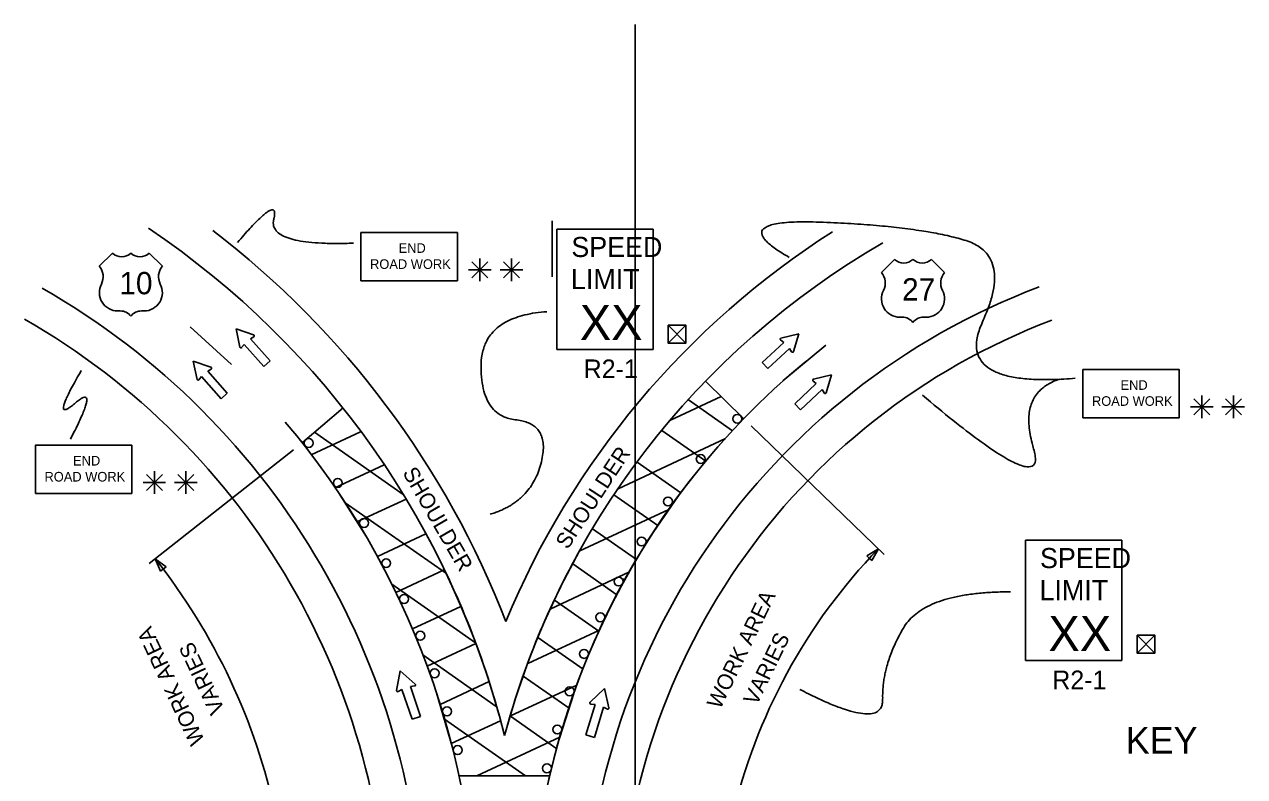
# Model space of a CAD drawing. Extents: x 16731 to 18475, y 7005 to 8303.
# Drawn here: x 16750 to 17297, y 7966 to 8303 of the extents above; entities that cross this region are included whole.
import ezdxf

# ---------------------------------------------------------------- set-up
doc = ezdxf.new("R2010")
doc.units = 0
for name, color, linetype in [('ALI_LEGAL_EX', 7, 'Continuous'), ('MT_SCRATCH_LEVEL_A', 7, 'Continuous'), ('MT_SCRATCH_LEVEL_E', 7, 'Continuous'), ('PAVT_EDGE_EX', 7, 'Continuous'), ('TRAFFIC_SIGNS_PR', 7, 'Continuous'), ('TYPICAL_EX', 7, 'Continuous'), ('TYPICAL_TEXT_DIMEN_EX', 7, 'Continuous'), ('TYPICAL_TEXT_DIMEN_PR', 7, 'Continuous')]:
    doc.layers.add(name, color=color, linetype=linetype)

msp = doc.modelspace()

# ---------------------------------------------------------------- linework, layer by layer
at = {"layer": 'ALI_LEGAL_EX'}
msp.add_line((17024.17, 8303.41), (17024.17, 7485.27), dxfattribs=at)
for points in [[(17024.17, 8278.41), (17024.17, 8303.41)], [(16987.01, 8190.21), (16987.01, 8215.21)], [(16843.15, 8150.81), (16824.71, 8167.69)], [(17090.38, 8143.53), (17109.68, 8159.42)], [(16904.53, 8072.26), (16891.17, 8093.39)], [(17029.34, 8071.03), (17043.42, 8091.69)], [(16942.06, 7979.47), (16935.11, 8003.48)], [(16989.13, 7979.42), (16996.62, 8003.27)]]:
    msp.add_lwpolyline(points, dxfattribs=at)
for centre, radius, start, end in [((17317.23, 7890.11), 340, 129.5666, 180), ((16589.23, 7890.11), 364, 0, 40.1909), ((17317.23, 7890.11), 340, 137.516, 180)]:
    msp.add_arc(centre, radius, start, end, dxfattribs=at)
at = {"layer": 'MT_SCRATCH_LEVEL_A'}
for p, q in [((17072.9, 8126.5), (17055.74, 8143.28)), ((17040, 8125.88), (17062.7, 8136.47)), ((16893.27, 8131.34), (16874.98, 8115.8)), ((17067.86, 8121.02), (17048.06, 8134.89)), ((16878.93, 8110.36), (16901.08, 8120.68)), ((16920.23, 8092.55), (16880.42, 8120.42)), ((17055.85, 8107.46), (17036.22, 8121.2)), ((17016.58, 8095.1), (17064.76, 8117.57)), ((16889.58, 8095.46), (16911.61, 8105.73)), ((17044.7, 8093.29), (17025.06, 8107.04)), ((17034.42, 8078.51), (17014.64, 8092.36)), ((16939.21, 8057.28), (16894.22, 8088.78)), ((16899.45, 8080.2), (16921.43, 8090.45)), ((16999.37, 8067.21), (17039.23, 8085.8)), ((17024.79, 8063.28), (17005.08, 8077.08)), ((16908.64, 8064.63), (16930.39, 8074.77)), ((17015.92, 8047.52), (16996.21, 8061.32)), ((16916.84, 8048.59), (16938.51, 8058.7)), ((16986.3, 8041.26), (17021.63, 8057.73)), ((17019.35, 8054.02), (17018.71, 8054.66)), ((16952.58, 8025.95), (16915.01, 8052.26)), ((17007.93, 8031.14), (16988.04, 8045.07)), ((16924.27, 8032.2), (16945.95, 8042.31)), ((16976.1, 8016.64), (17008.15, 8031.59)), ((17000.82, 8014.15), (16980.57, 8028.32)), ((16930.9, 8015.43), (16952.71, 8025.59)), ((16961.91, 7997.44), (16928.96, 8020.51)), ((16994.52, 7996.58), (16973.94, 8010.99)), ((16936.72, 7998.28), (16958.68, 8008.52)), ((16968.25, 7993.12), (16998.01, 8007)), ((16975.07, 7966.26), (16938.68, 7991.74)), ((16941.61, 7980.7), (16963.73, 7991.01)), ((16989.08, 7978.41), (16968.22, 7993.02)), ((16953.23, 7966.26), (16990.46, 7983.62)), ((16945.18, 7966.26), (16985.87, 7966.26)), ((16945.18, 7966.26), (16985.87, 7966.26)), ((16985.87, 7966.26), (16945.18, 7966.26)), ((16950.52, 7966.26), (16950.55, 7966.21)), ((16957.41, 7966.26), (16957.44, 7966.21)), ((16964.3, 7966.26), (16964.33, 7966.21)), ((16971.18, 7966.26), (16971.21, 7966.21)), ((16978.07, 7966.26), (16978.1, 7966.21)), ((16984.96, 7966.26), (16984.99, 7966.21))]:
    msp.add_line(p, q, dxfattribs=at)
for centre, radius, start, end in [((16589.23, 7890.11), 388, 14.0483, 28.2673), ((16589.23, 7890.11), 388, 14.0483, 28.2673), ((17317.23, 7890.11), 364, 151.1372, 165.0045), ((17317.23, 7890.11), 364, 151.1372, 165.0044)]:
    msp.add_arc(centre, radius, start, end, dxfattribs=at)
at = {"layer": 'MT_SCRATCH_LEVEL_E'}
for p, q in [((16845.2, 8166.75), (16846.93, 8158.61)), ((16853.1, 8164.09), (16845.2, 8166.75)), ((16845.2, 8166.75), (16846.93, 8158.61)), ((16853.1, 8164.09), (16845.2, 8166.75)), ((17097.64, 8164.6), (17089.54, 8162.65)), ((17097.64, 8164.6), (17089.54, 8162.65)), ((17095.19, 8156.63), (17097.64, 8164.6)), ((17095.19, 8156.63), (17097.64, 8164.6)), ((16847.74, 8158.42), (16848.86, 8159.83)), ((16847.74, 8158.42), (16848.86, 8159.83)), ((16848.86, 8159.83), (16857.66, 8149.91)), ((16848.86, 8159.83), (16857.66, 8149.91)), ((16851.66, 8162.31), (16853.2, 8163.26)), ((16851.66, 8162.31), (16853.2, 8163.26)), ((16860.46, 8152.39), (16851.66, 8162.31)), ((16860.46, 8152.39), (16851.66, 8162.31)), ((17090.82, 8160.75), (17081.15, 8151.68)), ((17090.82, 8160.75), (17081.15, 8151.68)), ((17083.71, 8148.95), (17093.38, 8158.02)), ((17083.71, 8148.95), (17093.38, 8158.02)), ((17089.37, 8161.83), (17090.82, 8160.75)), ((17089.37, 8161.83), (17090.82, 8160.75)), ((17093.38, 8158.02), (17094.36, 8156.51)), ((17093.38, 8158.02), (17094.36, 8156.51)), ((16826.05, 8152.29), (16827.77, 8144.14)), ((16833.95, 8149.62), (16826.05, 8152.29)), ((16826.05, 8152.29), (16827.77, 8144.14)), ((16833.95, 8149.62), (16826.05, 8152.29)), ((16832.51, 8147.85), (16834.05, 8148.79)), ((16832.51, 8147.85), (16834.05, 8148.79)), ((16841.3, 8137.93), (16832.51, 8147.85)), ((16841.3, 8137.93), (16832.51, 8147.85)), ((16857.66, 8149.91), (16860.46, 8152.39)), ((16857.66, 8149.91), (16860.46, 8152.39)), ((17081.15, 8151.68), (17083.71, 8148.95)), ((17081.15, 8151.68), (17083.71, 8148.95)), ((16828.59, 8143.95), (16829.71, 8145.37)), ((16828.59, 8143.95), (16829.71, 8145.37)), ((16829.71, 8145.37), (16838.5, 8135.45)), ((16829.71, 8145.37), (16838.5, 8135.45)), ((17105.41, 8142.28), (17095.74, 8133.21)), ((17105.41, 8142.28), (17095.74, 8133.21)), ((17103.97, 8143.36), (17105.41, 8142.28)), ((17103.97, 8143.36), (17105.41, 8142.28)), ((17112.23, 8146.13), (17104.14, 8144.18)), ((17112.23, 8146.13), (17104.14, 8144.18)), ((17109.78, 8138.15), (17112.23, 8146.13)), ((17109.78, 8138.15), (17112.23, 8146.13)), ((16838.5, 8135.45), (16841.3, 8137.93)), ((16838.5, 8135.45), (16841.3, 8137.93)), ((17098.3, 8130.48), (17107.97, 8139.55)), ((17098.3, 8130.48), (17107.97, 8139.55)), ((17107.97, 8139.55), (17108.96, 8138.04)), ((17107.97, 8139.55), (17108.96, 8138.04)), ((17095.74, 8133.21), (17098.3, 8130.48)), ((17095.74, 8133.21), (17098.3, 8130.48))]:
    msp.add_line(p, q, dxfattribs=at)
for centre, start, end in [((16852.95, 8163.65), 301.5941, 71.331), ((16852.95, 8163.65), 301.5941, 71.331), ((16847.38, 8158.71), 191.9827, 321.5217), ((16847.38, 8158.71), 191.9827, 321.5217), ((17089.66, 8162.2), 103.5817, 233.1207), ((17089.66, 8162.2), 103.5817, 233.1207), ((17094.75, 8156.77), 213.193, 342.93), ((17094.75, 8156.77), 213.193, 342.93), ((16833.8, 8149.18), 301.5941, 71.331), ((16833.8, 8149.18), 301.5941, 71.331), ((16828.23, 8144.25), 191.9827, 321.5217), ((16828.23, 8144.25), 191.9827, 321.5217), ((17104.25, 8143.73), 103.5817, 233.1207), ((17104.25, 8143.73), 103.5817, 233.1207), ((17109.34, 8138.3), 213.193, 342.93), ((17109.34, 8138.3), 213.193, 342.93)]:
    msp.add_arc(centre, 0.463, start, end, dxfattribs=at)
at = {"layer": 'PAVT_EDGE_EX'}
for centre, radius, start, end in [((16589.23, 7890.11), 388, 14.0482, 56.0497), ((16589.23, 7890.11), 404, 21.0961, 52.5595), ((17317.23, 7890.11), 380, 122.5612, 157.5011), ((17317.23, 7890.11), 364, 119.9839, 165.0045), ((17317.23, 7890.11), 316, 110.7433, 180), ((16589.23, 7890.11), 340, 0, 60.187), ((16589.23, 7890.11), 324, 0, 60.187), ((17317.23, 7890.11), 300, 110.7433, 180)]:
    msp.add_arc(centre, radius, start, end, dxfattribs=at)
at = {"layer": 'TRAFFIC_SIGNS_PR'}
for p, q in [((16989.09, 8211.57), (17032.29, 8211.57)), ((16989.09, 8157.57), (16989.09, 8211.57)), ((17032.29, 8157.57), (17032.29, 8211.57)), ((16989.09, 8157.57), (17032.29, 8157.57)), ((17199.23, 8072), (17242.43, 8072)), ((17199.23, 8018), (17199.23, 8072)), ((17242.43, 8018), (17242.43, 8072)), ((17199.23, 8018), (17242.43, 8018)), ((17010.42, 8005.42), (17004, 7999.28)), ((17012.44, 7996.75), (17010.42, 8005.42)), ((17006.2, 7998.21), (17002.13, 7984.67)), ((17004.28, 7998.44), (17006.2, 7998.21)), ((17005.96, 7983.52), (17010.02, 7997.07)), ((17010.02, 7997.07), (17011.74, 7996.2)), ((17002.13, 7984.67), (17005.96, 7983.52))]:
    msp.add_line(p, q, dxfattribs=at)
for points in [[(16901.25, 8188.38), (16944.45, 8188.38), (16944.45, 8209.98), (16901.25, 8209.98)], [(17224.95, 8126.93), (17268.15, 8126.93), (17268.15, 8148.53), (17224.95, 8148.53)], [(16755.27, 8092.97), (16798.47, 8092.97), (16798.47, 8114.57), (16755.27, 8114.57)]]:
    msp.add_lwpolyline(points, close=True, dxfattribs=at)
for centre in [(17069.98, 8126.45), (16877.77, 8115.58), (17053.61, 8108.4), (16890.85, 8097.69), (17038.9, 8089.35), (16902.58, 8079.73), (17027.06, 8071.39), (16912.53, 8061.68), (17016.76, 8053.45), (16920.57, 8045.58), (17008.58, 8037.42), (16927.82, 8029.11), (17001.26, 8020.98), (16934.24, 8012.29), (16994.81, 8004.17), (16939.83, 7995.18), (16989.26, 7987.05), (16944.57, 7977.82), (16984.61, 7969.66)]:
    msp.add_circle(centre, 2, dxfattribs=at)
for centre, start, end in [((17004.35, 7998.93), 133.7284, 263.2673), ((17011.95, 7996.65), 243.3397, 13.0766)]:
    msp.add_arc(centre, 0.494, start, end, dxfattribs=at)
at = {"layer": 'TYPICAL_EX'}
for p, q in [((16783.9, 8194.89), (16789.79, 8200.79)), ((16812.2, 8194.89), (16806.3, 8200.79)), ((17134.61, 8192.09), (17140.51, 8197.99)), ((17162.91, 8192.09), (17157.02, 8197.99)), ((16792.14, 8174.83), (16793.32, 8174.83)), ((16803.95, 8174.83), (16802.77, 8174.83)), ((17142.86, 8172.03), (17144.04, 8172.03)), ((17154.67, 8172.03), (17153.49, 8172.03))]:
    msp.add_line(p, q, dxfattribs=at)
for centre, radius, start, end in [((16793.92, 8205.08), 5.96, 226.1404, 313.8596), ((16802.17, 8205.08), 5.96, 226.1404, 313.8596), ((17144.64, 8202.28), 5.96, 226.1404, 313.8596), ((17152.89, 8202.28), 5.96, 226.1404, 313.8596), ((16778.31, 8190.17), 7.31, 333.0977, 40.1936), ((16817.78, 8190.17), 7.31, 139.8064, 206.9023), ((17129.03, 8187.37), 7.31, 333.0977, 40.1936), ((17168.5, 8187.37), 7.31, 139.8064, 206.9023), ((16792.16, 8183.08), 8.24, 152.6698, 269.9013), ((16803.94, 8183.08), 8.24, 270.0987, 27.3302), ((17142.87, 8180.27), 8.24, 152.6698, 269.9013), ((17154.65, 8180.27), 8.24, 270.0987, 27.3302), ((16793.34, 8168.93), 5.91, 37.1038, 90.1385), ((16802.76, 8168.93), 5.91, 89.8615, 142.8962), ((17144.05, 8166.12), 5.91, 37.1038, 90.1385), ((17153.47, 8166.12), 5.91, 89.8615, 142.8962)]:
    msp.add_arc(centre, radius, start, end, dxfattribs=at)
at = {"layer": 'TYPICAL_TEXT_DIMEN_PR'}
for p, q in [((16951.01, 8196.88), (16958.18, 8189.71)), ((16958.18, 8196.88), (16951.01, 8189.71)), ((16954.6, 8193.3), (16954.6, 8198.31)), ((16965.14, 8196.88), (16972.31, 8189.71)), ((16972.31, 8196.88), (16965.14, 8189.71)), ((16968.72, 8193.3), (16968.72, 8198.31)), ((16954.6, 8193.3), (16949.5, 8193.3)), ((16954.6, 8193.3), (16958.18, 8193.3)), ((16954.6, 8193.3), (16959.64, 8193.3)), ((16954.6, 8193.3), (16954.6, 8188.23)), ((16968.72, 8193.3), (16963.62, 8193.3)), ((16968.72, 8193.3), (16972.31, 8193.3)), ((16968.72, 8193.3), (16973.76, 8193.3)), ((16968.72, 8193.3), (16968.72, 8188.23)), ((17038.96, 8168.46), (17046.96, 8160.46)), ((17038.96, 8160.46), (17046.96, 8168.46)), ((17278.3, 8131.85), (17278.3, 8136.87)), ((17292.42, 8131.85), (17292.42, 8136.87)), ((17278.3, 8131.85), (17273.2, 8131.85)), ((17274.71, 8135.44), (17281.89, 8128.27)), ((17281.89, 8135.44), (17274.71, 8128.27)), ((17278.3, 8131.85), (17281.89, 8131.85)), ((17278.3, 8131.85), (17283.34, 8131.85)), ((17278.3, 8131.85), (17278.3, 8126.79)), ((17292.42, 8131.85), (17287.33, 8131.85)), ((17288.84, 8135.44), (17296.01, 8128.27)), ((17296.01, 8135.44), (17288.84, 8128.27)), ((17292.42, 8131.85), (17296.01, 8131.85)), ((17292.42, 8131.85), (17297.46, 8131.85)), ((17292.42, 8131.85), (17292.42, 8126.79)), ((17135.88, 8065.56), (17076.14, 8123.36)), ((16806.32, 8061.57), (16870.91, 8112.58)), ((16808.62, 8097.89), (16803.52, 8097.89)), ((16812.21, 8101.48), (16805.03, 8094.3)), ((16805.04, 8101.48), (16812.21, 8094.3)), ((16808.62, 8097.89), (16808.62, 8102.9)), ((16808.62, 8097.89), (16812.21, 8097.89)), ((16808.62, 8097.89), (16813.66, 8097.89)), ((16808.62, 8097.89), (16808.62, 8092.83)), ((16822.75, 8097.89), (16817.65, 8097.89)), ((16819.16, 8101.48), (16826.33, 8094.3)), ((16826.33, 8101.48), (16819.16, 8094.3)), ((16822.75, 8097.89), (16822.75, 8102.9)), ((16822.75, 8097.89), (16826.33, 8097.89)), ((16822.75, 8097.89), (16827.78, 8097.89)), ((16822.75, 8097.89), (16822.75, 8092.83)), ((17128.04, 8064.99), (17133.24, 8068.11)), ((17129.17, 8063.9), (17128.04, 8064.99)), ((17133.24, 8068.11), (17130.3, 8062.81)), ((16811.37, 8058.09), (16808.96, 8063.66)), ((16808.96, 8063.66), (16813.83, 8060.04)), ((16813.83, 8060.04), (16812.6, 8059.06)), ((17130.3, 8062.81), (17129.17, 8063.9)), ((16812.6, 8059.06), (16811.37, 8058.09)), ((17249.22, 8021.33), (17257.22, 8029.33)), ((17249.22, 8029.32), (17257.22, 8021.33)), ((16918.87, 8013.31), (16917.22, 8004.58)), ((16925.56, 8007.44), (16918.87, 8013.31)), ((16917.95, 8004.06), (16919.63, 8004.99)), ((16919.63, 8004.99), (16924.22, 7991.62)), ((16923.41, 8006.29), (16925.31, 8006.58)), ((16927.99, 7992.91), (16923.41, 8006.29)), ((16924.22, 7991.62), (16927.99, 7992.91))]:
    msp.add_line(p, q, dxfattribs=at)
for points in [[(17038.96, 8168.46), (17038.96, 8160.46), (17046.96, 8160.46), (17046.96, 8168.46)], [(17249.22, 8029.32), (17249.22, 8021.33), (17257.22, 8021.33), (17257.22, 8029.33)]]:
    msp.add_lwpolyline(points, close=True, dxfattribs=at)
for centre, radius, start, end in [((17317.23, 7890.11), 256, 135.9481, 167.0592), ((16589.23, 7890.11), 280, 12.0744, 38.3024), ((16925.22, 8007.07), 0.494, 278.9626, 48.6995), ((16917.71, 8004.5), 0.494, 169.3512, 298.8902)]:
    msp.add_arc(centre, radius, start, end, dxfattribs=at)
for points in [[(16845.84, 8205.53), (16865.05, 8228.13), (16859.21, 8203.85), (16897.9, 8205.25)], [(17093.29, 8198.86), (17063.19, 8216.18), (17149.79, 8213.21), (17193.82, 8200.09), (17166.17, 8140.07), (17221.55, 8144.62)], [(16959.12, 8083.6), (16977.64, 8089.16), (16986.46, 8124.29), (16955.05, 8127.66), (16955.11, 8172.4), (16984.59, 8174.52)], [(16775.83, 8148.1), (16761.37, 8123.47), (16784.58, 8143.32), (16770.92, 8117.31)], [(17153.1, 8137), (17210.34, 8088.44), (17195.3, 8138.1), (17214.48, 8144.25)], [(17098.05, 8005.01), (17135.55, 7985.55), (17134.79, 8015.8), (17153.79, 8048.82), (17192.42, 8048.82)]]:
    msp.add_open_spline(points, degree=2, dxfattribs=at)

# ---------------------------------------------------------------- texts
at = {"layer": 'TRAFFIC_SIGNS_PR'}
for s, height, p in [('SPEED', 9, (16995.58, 8199.04)), ('END', 4.31, (16918.12, 8200.9)), ('ROAD WORK', 4.31, (16905.31, 8193.71)), ('LIMIT', 9, (16995.4, 8184.64)), ('XX', 15.785, (16999.35, 8161.8)), ('R2-1', 8.37, (17001.1, 8144.7)), ('END', 4.31, (17241.83, 8139.45)), ('ROAD WORK', 4.31, (17229.01, 8132.27)), ('END', 4.31, (16772.15, 8105.49)), ('ROAD WORK', 4.31, (16759.33, 8098.31)), ('SPEED', 9, (17205.72, 8059.47)), ('LIMIT', 9, (17205.53, 8045.07)), ('XX', 15.785, (17209.48, 8022.23)), ('R2-1', 8.37, (17211.24, 8005.13))]:
    msp.add_text(s, height=height, dxfattribs=at).set_placement(p)
at = {"layer": 'TYPICAL_EX'}
for s, p in [('10', (16792.89, 8182.32)), ('27', (17143.87, 8179.52))]:
    msp.add_text(s, height=10, dxfattribs=at).set_placement(p)
at = {"layer": 'TYPICAL_TEXT_DIMEN_EX'}
msp.add_text('KEY', height=12, dxfattribs=at).set_placement((17244.22, 7976.17))
at = {"layer": 'TYPICAL_TEXT_DIMEN_PR'}
for s, rotation, p in [('SHOULDER', 56.8597, (16993.92, 8067.5)), ('SHOULDER', 300.0663, (16919.69, 8102.29)), ('WORK AREA', 64.0878, (17062.31, 7995.76)), ('WORK AREA', 115.1762, (16831.31, 7982.06)), ('VARIES', 64.0878, (17078.68, 7997.42)), ('VARIES', 115.1762, (16840.3, 7995.84))]:
    msp.add_text(s, height=7, rotation=rotation, dxfattribs=at).set_placement(p)

doc.saveas('drawing.dxf')
